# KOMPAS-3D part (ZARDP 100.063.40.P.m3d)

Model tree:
1. Операция без истории:1
2. Операция без истории:2
3. Операция без истории:3
4. Операция без истории:4
5. Операция без истории:5
6. Операция без истории:6
7. Операция без истории:7
8. Операция без истории:8
9. Операция без истории:9
10. Операция без истории:10
11. Операция без истории:11
12. Операция без истории:12
13. Операция без истории:13
14. Операция без истории:14
15. Операция без истории:15
16. Операция без истории:16
17. Операция без истории:17
18. Операция без истории:18
19. Операция без истории:19
20. Операция без истории:20
21. Операция без истории:21
22. Операция без истории:22
23. Операция без истории:23
24. Операция без истории:24
25. Операция без истории:25
26. Операция без истории:26
27. Операция без истории:27
28. Операция без истории:28
29. Операция без истории:29
30. Операция без истории:30
31. Операция без истории:31
32. Операция без истории:32
33. Операция без истории:33
34. Операция без истории:34
35. Операция без истории:35
36. Операция без истории:36
37. Операция без истории:37
38. Операция без истории:38
39. Операция без истории:39
40. Операция без истории:40
41. Операция без истории:41
42. Операция без истории:42
43. Операция без истории:43
44. Операция без истории:44
45. Операция без истории:45
46. Операция без истории:46
47. Операция без истории:47
48. Операция без истории:48
49. Операция без истории:49
50. Операция без истории:50
51. Операция без истории:51
52. Операция без истории:52
53. Поверхность без истории:1
54. Поверхность без истории:2
55. Поверхность без истории:3
56. Поверхность без истории:4
57. Поверхность без истории:5
58. Поверхность без истории:6
59. Поверхность без истории:7
60. Поверхность без истории:8

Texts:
  ЗАРДП 100.063.40-XX.Р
